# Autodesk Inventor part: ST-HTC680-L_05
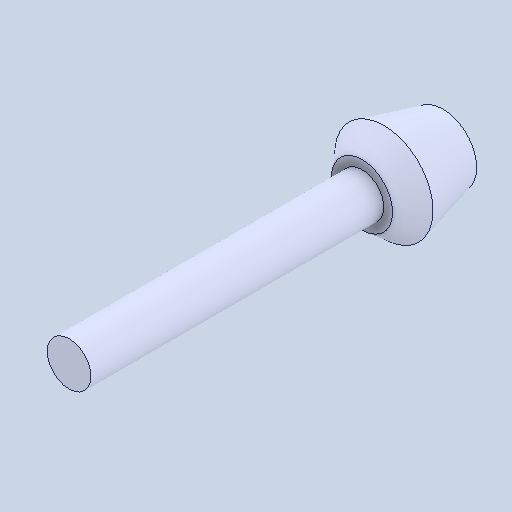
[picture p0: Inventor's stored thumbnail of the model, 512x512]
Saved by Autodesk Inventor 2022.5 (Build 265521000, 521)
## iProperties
Created: 2024-07
Part Number: ST-HTC680-L_05
Material: 一般
Document SubType Name: Modeling
Designer: ImaoCorp
Density: 1 g/cm^3
Appearance: 既定
Author: ImaoCorp
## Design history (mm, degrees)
feature "ST-HTC680-L_05"
node "ソリッド1"
